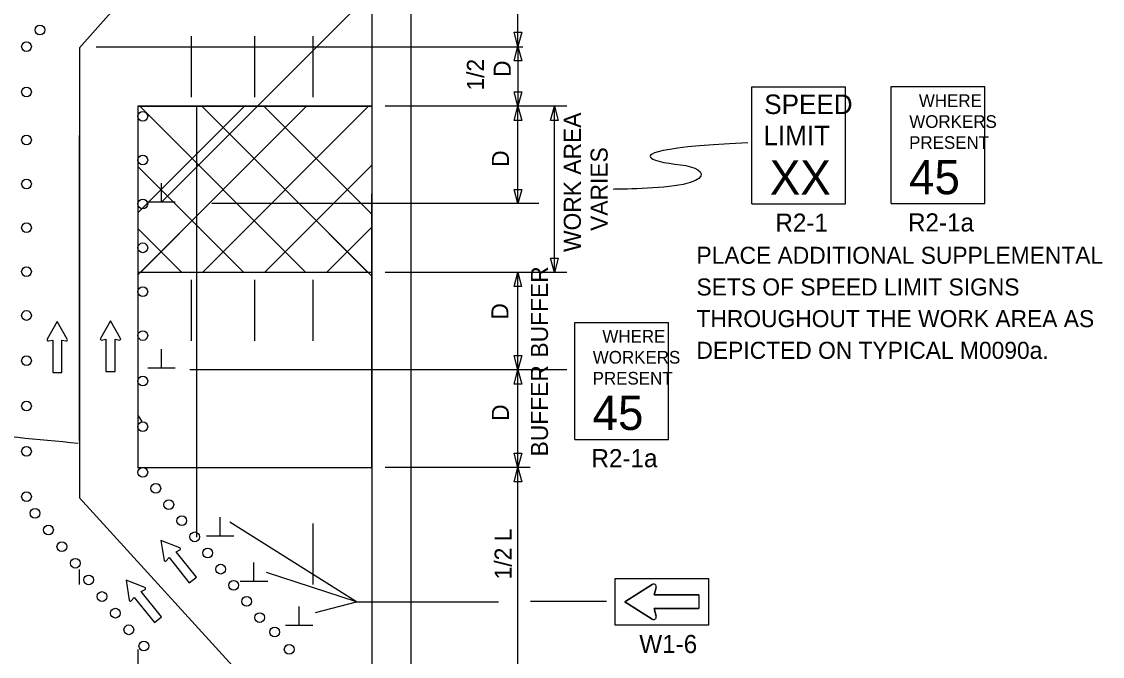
# Model space of a CAD drawing. Extents: x 16726 to 19504, y 5932 to 7446.
# Drawn here: x 16978.9 to 17422.7, y 6189.6 to 6450.1 of the extents above; entities that cross this region are included whole.
import ezdxf

# ---------------------------------------------------------------- set-up
doc = ezdxf.new("R2010")
doc.units = 0
for name, color, linetype in [('ALI_LEGAL_EX', 7, 'Continuous'), ('MT_SCRATCH_LEVEL_A', 7, 'Continuous'), ('MT_SCRATCH_LEVEL_E', 7, 'Continuous'), ('PAVT_EDGE_EX', 7, 'Continuous'), ('TRAFFIC_SIGNS_PR', 7, 'Continuous'), ('TYPICAL_TEXT_DIMEN_PR', 7, 'Continuous')]:
    doc.layers.add(name, color=color, linetype=linetype)

msp = doc.modelspace()

# ---------------------------------------------------------------- linework, layer by layer
at = {"layer": 'ALI_LEGAL_EX'}
for points in [[(17048.71, 6419.12), (17048.71, 6444.12)], [(17074.71, 6419.12), (17074.71, 6444.12)], [(17098.71, 6419.12), (17098.71, 6444.12)], [(17002.71, 6277.84), (17002.71, 6403.27)], [(17002.71, 6319.65), (17002.71, 6344.12)], [(17048.71, 6319.12), (17048.71, 6344.12)], [(17074.71, 6319.12), (17074.71, 6344.12)], [(17098.71, 6319.12), (17098.71, 6344.12)], [(17098.71, 6219.12), (17098.71, 6244.12)], [(17002.71, 6219.12), (17002.71, 6225.28)]]:
    msp.add_lwpolyline(points, dxfattribs=at)
at = {"layer": 'MT_SCRATCH_LEVEL_A'}
for p, q in [((17026.71, 6415.36), (17122.71, 6415.36)), ((17122.71, 6415.36), (17026.71, 6415.36)), ((17026.71, 6371.56), (17070.51, 6415.36)), ((17026.71, 6346.1), (17095.97, 6415.36)), ((17095.68, 6347.12), (17027.45, 6415.36)), ((17122.71, 6345.56), (17052.91, 6415.36)), ((17053.19, 6347.12), (17121.43, 6415.36)), ((17122.71, 6371.01), (17078.37, 6415.36)), ((17070.23, 6347.12), (17026.71, 6390.64)), ((17078.65, 6347.12), (17122.71, 6391.18)), ((17027.74, 6347.12), (17059.97, 6379.36)), ((17121.14, 6347.12), (17088.91, 6379.36)), ((17122.71, 6379.36), (17122.71, 6267.12)), ((17122.71, 6379.36), (17122.71, 6267.12)), ((17122.71, 6295.18), (17122.71, 6379.36)), ((17044.77, 6347.12), (17026.71, 6365.19)), ((17104.11, 6347.12), (17122.71, 6365.73)), ((17026.71, 6295.18), (17026.71, 6295.18)), ((17026.74, 6288.32), (17028.31, 6285.93)), ((17026.71, 6267.12), (17122.71, 6267.12)), ((17026.71, 6267.12), (17122.71, 6267.12))]:
    msp.add_line(p, q, dxfattribs=at)
at = {"layer": 'MT_SCRATCH_LEVEL_E'}
for p, q in [((16993.55, 6326.98), (16989.44, 6319.74)), ((16993.55, 6326.98), (16989.44, 6319.74)), ((16997.69, 6319.74), (16993.55, 6326.98)), ((16997.69, 6319.74), (16993.55, 6326.98)), ((17015.42, 6327.32), (17011.31, 6320.08)), ((17015.42, 6327.32), (17011.31, 6320.08)), ((17019.57, 6320.08), (17015.42, 6327.32)), ((17019.57, 6320.08), (17015.42, 6327.32)), ((16989.92, 6319.05), (16991.7, 6319.37)), ((16989.92, 6319.05), (16991.7, 6319.37)), ((16991.7, 6319.37), (16991.7, 6306.11)), ((16991.7, 6319.37), (16991.7, 6306.11)), ((16995.44, 6306.11), (16995.44, 6319.37)), ((16995.44, 6319.37), (16997.21, 6319.05)), ((16995.44, 6306.11), (16995.44, 6319.37)), ((16995.44, 6319.37), (16997.21, 6319.05)), ((17011.8, 6319.4), (17013.57, 6319.71)), ((17011.8, 6319.4), (17013.57, 6319.71)), ((17013.57, 6319.71), (17013.57, 6306.46)), ((17013.57, 6319.71), (17013.57, 6306.46)), ((17017.31, 6306.46), (17017.31, 6319.71)), ((17017.31, 6319.71), (17019.09, 6319.4)), ((17017.31, 6306.46), (17017.31, 6319.71)), ((17017.31, 6319.71), (17019.09, 6319.4)), ((16991.7, 6306.11), (16995.44, 6306.11)), ((16991.7, 6306.11), (16995.44, 6306.11)), ((17013.57, 6306.46), (17017.31, 6306.46)), ((17013.57, 6306.46), (17017.31, 6306.46)), ((17036.14, 6237.18), (17037.48, 6228.96)), ((17043.92, 6234.14), (17036.14, 6237.18)), ((17036.14, 6237.18), (17037.48, 6228.96)), ((17043.92, 6234.14), (17036.14, 6237.18)), ((17042.39, 6232.44), (17043.97, 6233.31)), ((17042.39, 6232.44), (17043.97, 6233.31)), ((17050.7, 6222.11), (17042.39, 6232.44)), ((17050.7, 6222.11), (17042.39, 6232.44)), ((17038.29, 6228.73), (17039.47, 6230.09)), ((17038.29, 6228.73), (17039.47, 6230.09)), ((17039.47, 6230.09), (17047.79, 6219.77)), ((17039.47, 6230.09), (17047.79, 6219.77)), ((17047.79, 6219.77), (17050.7, 6222.11)), ((17047.79, 6219.77), (17050.7, 6222.11)), ((17021.81, 6220.88), (17023.15, 6212.66)), ((17029.58, 6217.84), (17021.81, 6220.88)), ((17021.81, 6220.88), (17023.15, 6212.66)), ((17029.58, 6217.84), (17021.81, 6220.88)), ((17028.05, 6216.14), (17029.64, 6217.01)), ((17028.05, 6216.14), (17029.64, 6217.01)), ((17023.95, 6212.43), (17025.14, 6213.79)), ((17023.95, 6212.43), (17025.14, 6213.79)), ((17025.14, 6213.79), (17033.45, 6203.46)), ((17025.14, 6213.79), (17033.45, 6203.46)), ((17036.37, 6205.81), (17028.05, 6216.14)), ((17036.37, 6205.81), (17028.05, 6216.14)), ((17033.45, 6203.46), (17036.37, 6205.81)), ((17033.45, 6203.46), (17036.37, 6205.81))]:
    msp.add_line(p, q, dxfattribs=at)
for centre, start, end in [((16989.84, 6319.52), 150.4248, 279.9638), ((16989.84, 6319.52), 150.4248, 279.9638), ((16997.28, 6319.52), 260.0362, 29.7731), ((16997.28, 6319.52), 260.0362, 29.7731), ((17011.72, 6319.86), 150.4248, 279.9638), ((17011.72, 6319.86), 150.4248, 279.9638), ((17019.16, 6319.86), 260.0362, 29.7731), ((17019.16, 6319.86), 260.0362, 29.7731), ((17043.74, 6233.71), 298.877, 68.6139), ((17043.74, 6233.71), 298.877, 68.6139), ((17037.94, 6229.04), 189.2656, 318.8046), ((17037.94, 6229.04), 189.2656, 318.8046), ((17029.4, 6217.41), 298.877, 68.6139), ((17029.4, 6217.41), 298.877, 68.6139), ((17023.61, 6212.74), 189.2656, 318.8046), ((17023.61, 6212.74), 189.2656, 318.8046)]:
    msp.add_arc(centre, 0.463, start, end, dxfattribs=at)
at = {"layer": 'PAVT_EDGE_EX'}
for p, q in [((17122.71, 6865.32), (17122.71, 6079.93)), ((17138.71, 6865.32), (17138.71, 6112.72)), ((17002.71, 6439.27), (17002.71, 6254.65)), ((17026.71, 6415.36), (17026.71, 6266.77)), ((17050.71, 6415.36), (17050.71, 6238.46)), ((17026.71, 6192.44), (17026.71, 6079.72))]:
    msp.add_line(p, q, dxfattribs=at)
msp.add_lwpolyline([(17122.71, 6347.12), (17026.71, 6347.12), (17026.71, 6267.12), (17122.71, 6267.12)], close=True, dxfattribs=at)
at = {"layer": 'TRAFFIC_SIGNS_PR'}
for p, q in [((17278.83, 6423.29), (17317.23, 6423.29)), ((17278.83, 6375.29), (17278.83, 6423.29)), ((17317.23, 6375.29), (17317.23, 6423.29)), ((17336.03, 6423.38), (17374.43, 6423.38)), ((17336.03, 6375.38), (17336.03, 6423.38)), ((17374.43, 6375.38), (17374.43, 6423.38)), ((17278.83, 6375.29), (17317.23, 6375.29)), ((17336.03, 6375.38), (17374.43, 6375.38)), ((17206.08, 6326.63), (17244.48, 6326.63)), ((17206.08, 6278.63), (17206.08, 6326.63)), ((17244.48, 6278.63), (17244.48, 6326.63)), ((17206.08, 6278.63), (17244.48, 6278.63)), ((17237.78, 6219.08), (17226.62, 6211.98)), ((17238.63, 6214.78), (17239.47, 6217.84)), ((17257.02, 6214.78), (17238.63, 6214.78)), ((17257.02, 6214.78), (17257.02, 6209.18)), ((17226.62, 6211.98), (17237.78, 6204.87)), ((17239.47, 6206.11), (17238.63, 6209.18)), ((17238.63, 6209.18), (17257.02, 6209.18))]:
    msp.add_line(p, q, dxfattribs=at)
msp.add_lwpolyline([(17261.02, 6202.38), (17222.62, 6202.38), (17222.62, 6221.57), (17261.02, 6221.57)], close=True, dxfattribs=at)
for points in [[(17237.78, 6204.87), (17226.62, 6211.98), (17237.78, 6219.08)], [(17239.47, 6217.84), (17238.63, 6214.78), (17257.02, 6214.78), (17257.02, 6209.18), (17238.63, 6209.18), (17239.47, 6206.11)]]:
    msp.add_lwpolyline(points, dxfattribs=at)
for centre in [(16986.45, 6446.65), (16980.95, 6439.82), (16980.95, 6439.82), (16980.95, 6421.23), (17028.71, 6411.24), (16980.95, 6401.47), (17028.71, 6393.24), (16980.95, 6383.47), (17028.71, 6375.24), (16980.95, 6365.47), (17028.71, 6357.24), (16980.95, 6347.47), (17028.71, 6339.24), (16980.95, 6329.47), (17028.71, 6321.24), (16980.95, 6310.89), (17028.71, 6302.54), (16980.95, 6292.3), (17028.71, 6283.83), (16980.95, 6273.71), (17028.71, 6265.12), (16980.95, 6255.13), (17034.04, 6258.5), (17039.38, 6251.88), (16984.47, 6248.3), (17044.71, 6245.25), (16989.97, 6241.47), (17050.04, 6238.63), (16995.47, 6234.64), (17055.38, 6232.01), (17000.97, 6227.81), (17060.71, 6225.38), (17006.47, 6220.97), (17066.04, 6218.76), (17011.97, 6214.14), (17071.38, 6212.14), (17017.47, 6207.31), (17076.71, 6205.51), (17022.97, 6200.48), (17082.81, 6199.58), (17082.81, 6199.58), (17029.14, 6193.86), (17029.14, 6193.86), (17088.81, 6192.44)]:
    msp.add_circle(centre, 2, dxfattribs=at)
for centre, start, end in [((17238.38, 6218.13), 344.6731, 122.4696), ((17238.38, 6218.13), 344.6731, 122.4696), ((17238.38, 6205.82), 237.5304, 15.3269), ((17238.38, 6205.82), 237.5304, 15.3269)]:
    msp.add_arc(centre, 1.12, start, end, dxfattribs=at)
at = {"layer": 'TYPICAL_TEXT_DIMEN_PR'}
for p, q in [((17002.71, 6439.27), (17074.68, 6520.48)), ((17182.71, 6440.47), (17182.71, 6520.14)), ((17170.12, 6509.61), (17036.34, 6376.02)), ((17182.71, 6439.82), (17181.14, 6445.68)), ((17181.14, 6445.68), (17182.71, 6445.68)), ((17182.71, 6445.68), (17184.28, 6445.68)), ((17184.28, 6445.68), (17182.71, 6439.82)), ((17184.69, 6439.62), (17009.54, 6439.62)), ((17181.14, 6433.96), (17182.71, 6439.82)), ((17182.71, 6439.82), (17184.28, 6433.96)), ((17182.71, 6439.82), (17182.71, 6415.36)), ((17182.71, 6433.96), (17181.14, 6433.96)), ((17184.28, 6433.96), (17182.71, 6433.96)), ((17182.71, 6415.36), (17181.14, 6421.22)), ((17181.14, 6421.22), (17182.71, 6421.22)), ((17182.71, 6421.22), (17184.28, 6421.22)), ((17184.28, 6421.22), (17182.71, 6415.36)), ((17202.87, 6415.36), (17128.21, 6415.36)), ((17181.14, 6409.49), (17182.71, 6415.36)), ((17182.71, 6375.36), (17182.71, 6415.36)), ((17182.71, 6415.36), (17184.28, 6409.49)), ((17196.14, 6409.49), (17197.71, 6415.36)), ((17197.71, 6347.12), (17197.71, 6415.36)), ((17197.71, 6415.36), (17199.28, 6409.49)), ((17182.71, 6409.49), (17181.14, 6409.49)), ((17184.28, 6409.49), (17182.71, 6409.49)), ((17197.71, 6409.49), (17196.14, 6409.49)), ((17199.28, 6409.49), (17197.71, 6409.49)), ((17036.34, 6376.02), (17036.34, 6383.81)), ((17182.71, 6375.36), (17181.14, 6381.22)), ((17181.14, 6381.22), (17182.71, 6381.22)), ((17182.71, 6381.22), (17184.28, 6381.22)), ((17184.28, 6381.22), (17182.71, 6375.36)), ((17041.96, 6376.02), (17030.71, 6376.02)), ((17191.33, 6375.36), (17057.11, 6375.36)), ((17197.71, 6347.12), (17196.14, 6352.99)), ((17196.14, 6352.99), (17197.71, 6352.99)), ((17197.71, 6352.99), (17199.28, 6352.99)), ((17199.28, 6352.99), (17197.71, 6347.12)), ((17202.87, 6347.12), (17128.21, 6347.12)), ((17181.12, 6341.3), (17182.69, 6347.16)), ((17182.69, 6347.16), (17184.26, 6341.3)), ((17182.7, 6307.14), (17182.7, 6347.15)), ((17182.69, 6341.3), (17181.12, 6341.3)), ((17184.26, 6341.3), (17182.69, 6341.3)), ((17036.34, 6307.81), (17036.34, 6315.6)), ((17182.7, 6307.14), (17181.13, 6313.01)), ((17181.13, 6313.01), (17182.7, 6313.01)), ((17182.7, 6313.01), (17184.27, 6313.01)), ((17184.27, 6313.01), (17182.7, 6307.14)), ((17041.96, 6307.81), (17030.71, 6307.81)), ((17202.82, 6307.12), (17047.98, 6307.12)), ((17181.13, 6301.28), (17182.7, 6307.14)), ((17182.7, 6307.14), (17184.27, 6301.28)), ((17182.71, 6267.12), (17182.71, 6307.13)), ((17182.7, 6301.28), (17181.13, 6301.28)), ((17184.27, 6301.28), (17182.7, 6301.28)), ((17182.71, 6267.12), (17181.14, 6272.99)), ((17181.14, 6272.99), (17182.71, 6272.99)), ((17182.71, 6272.99), (17184.28, 6272.99)), ((17184.28, 6272.99), (17182.71, 6267.12)), ((17187.71, 6267.12), (17128.21, 6267.12)), ((17181.14, 6261.26), (17182.71, 6267.12)), ((17182.71, 6267.12), (17184.28, 6261.26)), ((17182.71, 6179.17), (17182.71, 6267.12)), ((17182.71, 6261.26), (17181.14, 6261.26)), ((17184.28, 6261.26), (17182.71, 6261.26)), ((17002.71, 6254.65), (17075.64, 6174.71)), ((17060.43, 6238.94), (17060.43, 6246.72)), ((17116.4, 6211.96), (17064.46, 6244.63)), ((17066.05, 6238.94), (17054.8, 6238.94)), ((17074.36, 6220.37), (17074.36, 6228.16)), ((17116.4, 6211.96), (17079.43, 6224.02)), ((17079.98, 6220.37), (17068.73, 6220.37)), ((17092.91, 6202.29), (17092.91, 6210.08)), ((17099.67, 6207.54), (17116.4, 6211.96)), ((17116.4, 6211.96), (17174.71, 6211.96)), ((17187.93, 6212.18), (17219.11, 6212.18)), ((17098.53, 6202.29), (17087.28, 6202.29))]:
    msp.add_line(p, q, dxfattribs=at)
for points, degree in [([(17277.12, 6400.37), (17234.24, 6398.29), (17234.94, 6391.63), (17259.39, 6391.63), (17259.39, 6381.73), (17223.98, 6381.24), (17221.85, 6381.24)], 3), ([(17002.21, 6276.96), (16908.69, 6286.73), (16904.45, 6272.41), (16928.94, 6271.51), (16936.35, 6262.11), (16884.59, 6268.69), (16886.54, 6268.69)], 2)]:
    msp.add_open_spline(points, degree=degree, dxfattribs=at)

# ---------------------------------------------------------------- texts
at = {"layer": 'TRAFFIC_SIGNS_PR'}
for s, height, p in [('SPEED', 8, (17283.86, 6412.15)), ('WHERE', 5.2, (17347.34, 6415.06)), ('WORKERS', 5.2, (17343.41, 6406.46)), ('LIMIT', 8, (17283.53, 6399.35)), ('PRESENT', 5.2, (17343.34, 6397.86)), ('XX', 14.031, (17286.14, 6379.05)), ('45', 14.031, (17343.33, 6379.23)), ('R2-1', 7.44, (17288.44, 6363.85)), ('R2-1a', 7.44, (17342.88, 6363.94)), ('PLACE ADDITIONAL SUPPLEMENTAL', 7, (17256.03, 6350.68)), ('SETS OF SPEED LIMIT SIGNS', 7, (17256.03, 6337.68)), ('THROUGHOUT THE WORK AREA AS', 7, (17256.03, 6324.68)), ('WHERE', 5.2, (17217.39, 6318.32)), ('WORKERS', 5.2, (17213.46, 6309.72)), ('DEPICTED ON TYPICAL M0090a.', 7, (17256.03, 6311.68)), ('PRESENT', 5.2, (17213.4, 6301.12)), ('45', 14.031, (17213.39, 6282.49)), ('R2-1a', 7.44, (17212.93, 6267.19)), ('W1-6', 7.44, (17232.56, 6190.94))]:
    msp.add_text(s, height=height, dxfattribs=at).set_placement(p)
at = {"layer": 'TYPICAL_TEXT_DIMEN_PR'}
for s, p in [('1/2', (17168.78, 6421.78)), ('D', (17179.78, 6427.35)), ('WORK AREA', (17208.56, 6355.53)), ('D', (17179.06, 6390.46)), ('VARIES', (17219.56, 6364.18)), ('BUFFER', (17195.06, 6312.2)), ('D', (17178.8, 6327.76)), ('BUFFER', (17195.06, 6271.64)), ('D', (17179.02, 6286.22)), ('1/2 L', (17180.15, 6221.18))]:
    msp.add_text(s, height=7, rotation=90, dxfattribs=at).set_placement(p)

doc.saveas('drawing.dxf')
